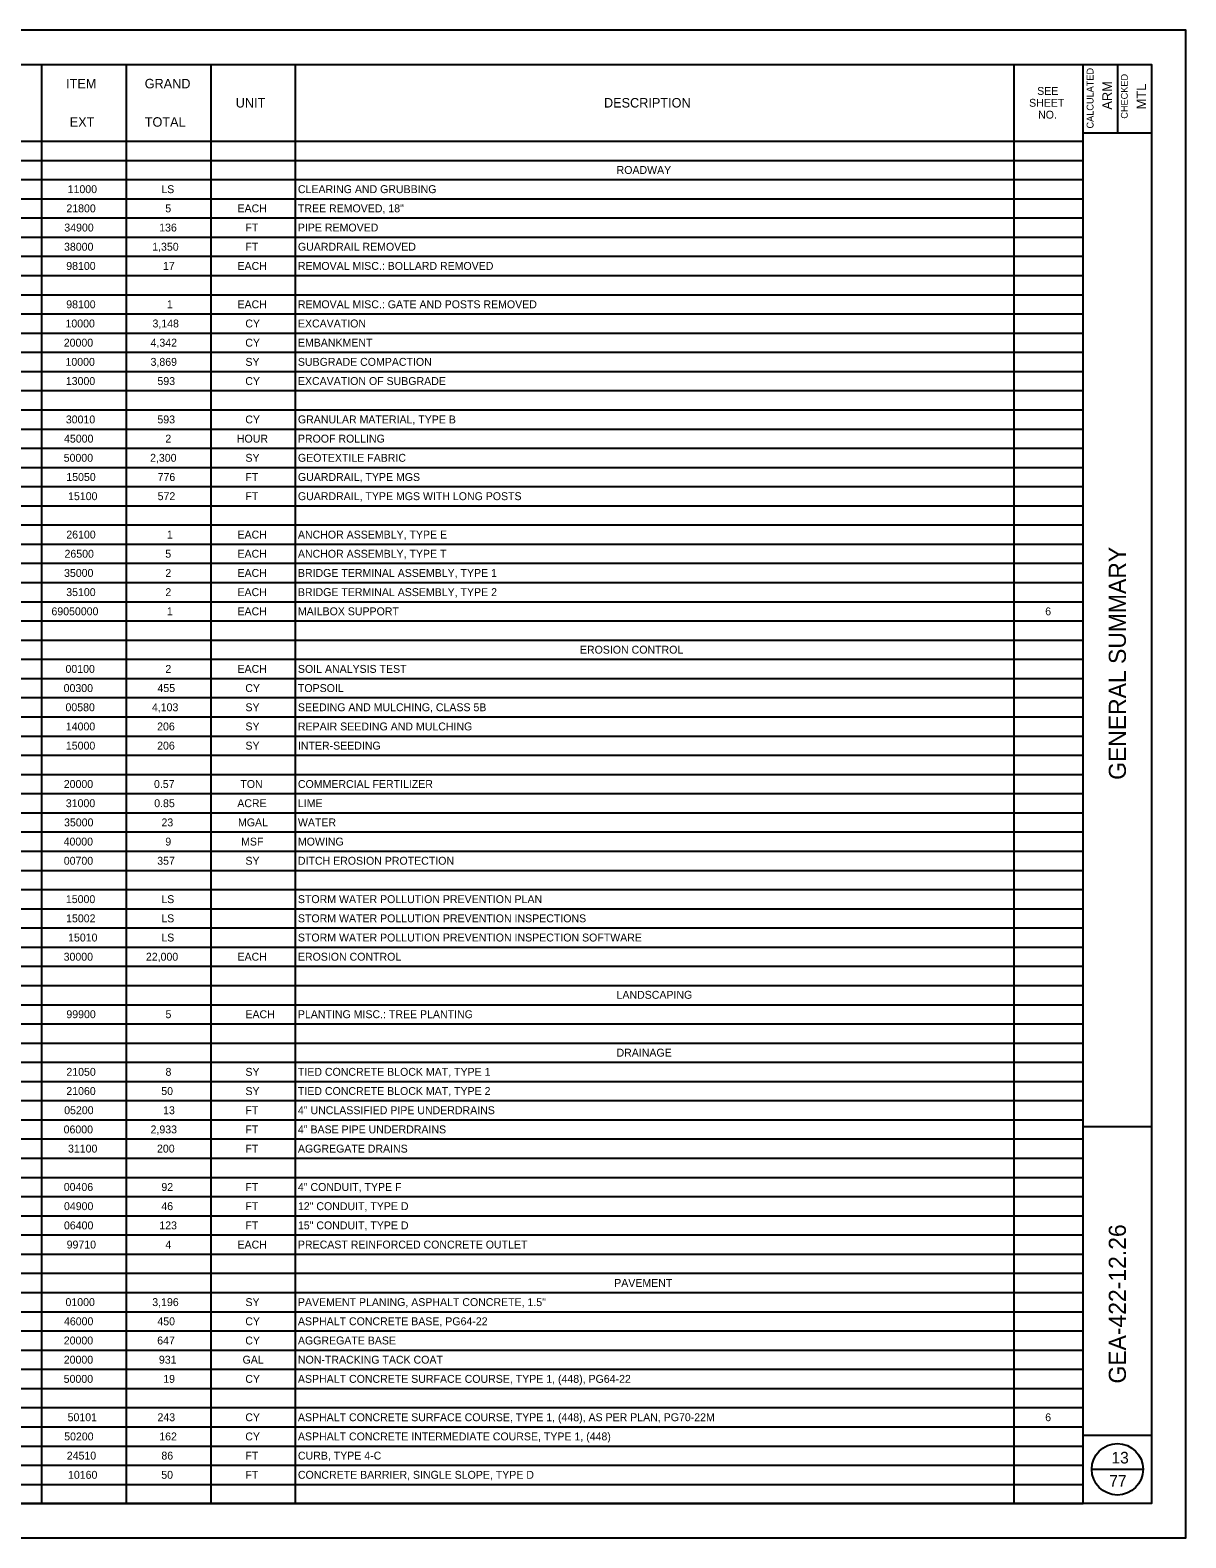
# Model space of a CAD drawing. Extents: x 0 to 34, y 0 to 22.
# Drawn here: x 17.13 to 34, y 0 to 22 of the extents above; entities that cross this region are included whole.
import ezdxf

# ---------------------------------------------------------------- set-up
doc = ezdxf.new("R2010")
doc.units = 0
for name, color, linetype in [('SH_Border', 7, 'Continuous'), ('SH_Cut_Line', 7, 'Continuous'), ('SH_Data', 7, 'Continuous'), ('SH_Text', 7, 'Continuous')]:
    doc.layers.add(name, color=color, linetype=linetype)

msp = doc.modelspace()

# ---------------------------------------------------------------- linework, layer by layer
at = {"layer": 'SH_Border'}
for p, q in [((32.5, 0.5), (32.5, 21.5)), ((33, 21.5), (33, 20.5)), ((32.5, 20.5), (33.5, 20.5)), ((32.5, 6), (33.5, 6)), ((32.5, 1.5), (33.5, 1.5))]:
    msp.add_line(p, q, dxfattribs=at)
msp.add_lwpolyline([(2, 21.5), (33.5, 21.5), (33.5, 0.5), (2, 0.5)], close=True, dxfattribs=at)
at = {"layer": 'SH_Cut_Line'}
msp.add_lwpolyline([(0, 0), (34, 0), (34, 22), (0, 22)], close=True, dxfattribs=at)
at = {"layer": 'SH_Data'}
msp.add_line((32.625, 1), (33.375, 1), dxfattribs=at)
msp.add_circle((33, 1), 0.375, dxfattribs=at)
at = {"layer": 'SH_Text'}
for p, q in [((2, 21.5), (32.5, 21.5)), ((17.299, 0.5), (17.299, 21.5)), ((18.535, 0.5), (18.535, 21.5)), ((19.77, 0.5), (19.77, 21.5)), ((21.005, 0.5), (21.005, 21.5)), ((31.495, 0.5), (31.495, 21.5)), ((32.5, 0.5), (32.5, 21.5)), ((14.055, 20.38), (32.5, 20.38)), ((19.77, 20.38), (32.5, 20.38)), ((2, 20.1), (32.5, 20.1)), ((2, 19.82), (32.5, 19.82)), ((2, 19.54), (32.5, 19.54)), ((2, 19.26), (32.5, 19.26)), ((2, 18.98), (32.5, 18.98)), ((2, 18.7), (32.5, 18.7)), ((2, 18.42), (32.5, 18.42)), ((2, 18.14), (32.5, 18.14)), ((2, 17.86), (32.5, 17.86)), ((2, 17.58), (32.5, 17.58)), ((2, 17.3), (32.5, 17.3)), ((2, 17.02), (32.5, 17.02)), ((2, 16.74), (32.5, 16.74)), ((2, 16.46), (32.5, 16.46)), ((2, 16.18), (32.5, 16.18)), ((2, 15.9), (32.5, 15.9)), ((2, 15.62), (32.5, 15.62)), ((2, 15.34), (32.5, 15.34)), ((2, 15.06), (32.5, 15.06)), ((2, 14.78), (32.5, 14.78)), ((2, 14.5), (32.5, 14.5)), ((2, 14.22), (32.5, 14.22)), ((2, 13.94), (32.5, 13.94)), ((2, 13.66), (32.5, 13.66)), ((2, 13.38), (32.5, 13.38)), ((2, 13.1), (32.5, 13.1)), ((2, 12.82), (32.5, 12.82)), ((2, 12.54), (32.5, 12.54)), ((2, 12.26), (32.5, 12.26)), ((2, 11.98), (32.5, 11.98)), ((2, 11.7), (32.5, 11.7)), ((2, 11.42), (32.5, 11.42)), ((2, 11.14), (32.5, 11.14)), ((2, 10.86), (32.5, 10.86)), ((2, 10.58), (32.5, 10.58)), ((2, 10.3), (32.5, 10.3)), ((2, 10.02), (32.5, 10.02)), ((2, 9.74), (32.5, 9.74)), ((2, 9.46), (32.5, 9.46)), ((2, 9.18), (32.5, 9.18)), ((2, 8.9), (32.5, 8.9)), ((2, 8.62), (32.5, 8.62)), ((2, 8.34), (32.5, 8.34)), ((2, 8.06), (32.5, 8.06)), ((2, 7.78), (32.5, 7.78)), ((2, 7.5), (32.5, 7.5)), ((2, 7.22), (32.5, 7.22)), ((2, 6.94), (32.5, 6.94)), ((2, 6.66), (32.5, 6.66)), ((2, 6.38), (32.5, 6.38)), ((2, 6.1), (32.5, 6.1)), ((2, 5.82), (32.5, 5.82)), ((2, 5.54), (32.5, 5.54)), ((2, 5.26), (32.5, 5.26)), ((2, 4.98), (32.5, 4.98)), ((2, 4.7), (32.5, 4.7)), ((2, 4.42), (32.5, 4.42)), ((2, 4.14), (32.5, 4.14)), ((2, 3.86), (32.5, 3.86)), ((2, 3.58), (32.5, 3.58)), ((2, 3.3), (32.5, 3.3)), ((2, 3.02), (32.5, 3.02)), ((2, 2.74), (32.5, 2.74)), ((2, 2.46), (32.5, 2.46)), ((2, 2.18), (32.5, 2.18)), ((2, 1.9), (32.5, 1.9)), ((2, 1.62), (32.5, 1.62)), ((2, 1.34), (32.5, 1.34)), ((2, 1.06), (32.5, 1.06)), ((2, 0.78), (32.5, 0.78)), ((2, 0.5), (32.5, 0.5))]:
    msp.add_line(p, q, dxfattribs=at)

# ---------------------------------------------------------------- texts
at = {"layer": 'SH_Data'}
for s, height, p in [('CALCULATED', 0.1, (32.652, 20.565)), ('CHECKED', 0.1, (33.152, 20.708)), ('ARM', 0.14, (32.92, 20.84)), ('MTL', 0.14, (33.42, 20.844)), ('GENERAL SUMMARY', 0.25, (33.125, 11.061)), ('GEA-422-12.26', 0.25, (33.125, 2.252))]:
    msp.add_text(s, height=height, rotation=90, dxfattribs=at).set_placement(p)
for s, p in [('13', (32.914, 1.085)), ('77', (32.882, 0.745))]:
    msp.add_text(s, height=0.17, dxfattribs=at).set_placement(p)
at = {"layer": 'SH_Text'}
for s, height, p in [('ITEM', 0.1384, (17.654, 21.151)), ('GRAND', 0.1384, (18.801, 21.151)), ('SEE', 0.1153, (31.83, 21.055)), ('UNIT', 0.1384, (20.13, 20.871)), ('DESCRIPTION', 0.13841, (25.506, 20.871)), ('SHEET', 0.1153, (31.712, 20.882)), ('EXT', 0.1384, (17.707, 20.591)), ('TOTAL', 0.1384, (18.802, 20.591)), ('NO.', 0.1153, (31.843, 20.709)), ('ROADWAY', 0.1153, (25.69, 19.902)), ('11000', 0.1153, (17.677, 19.622)), ('LS', 0.1153, (19.044, 19.622)), ('CLEARING AND GRUBBING ', 0.11534, (21.038, 19.622)), ('21800', 0.1153, (17.658, 19.342)), ('5', 0.115, (19.102, 19.342)), ('EACH', 0.1153, (20.156, 19.342)), ('TREE REMOVED, 18" ', 0.11534, (21.038, 19.342)), ('34900', 0.1153, (17.628, 19.062)), ('136', 0.1153, (19.013, 19.062)), ('FT', 0.1153, (20.272, 19.062)), ('PIPE REMOVED ', 0.11534, (21.038, 19.062)), ('38000', 0.1153, (17.624, 18.782)), ('1,350', 0.1153, (18.911, 18.782)), ('FT', 0.1153, (20.272, 18.782)), ('GUARDRAIL REMOVED ', 0.11534, (21.038, 18.782)), ('98100', 0.1153, (17.656, 18.502)), ('17', 0.1153, (19.068, 18.502)), ('EACH', 0.1153, (20.156, 18.502)), ('REMOVAL MISC.: BOLLARD REMOVED', 0.11534, (21.038, 18.502)), ('98100', 0.1153, (17.656, 17.942)), ('1', 0.115, (19.125, 17.942)), ('EACH', 0.1153, (20.156, 17.942)), ('REMOVAL MISC.: GATE AND POSTS REMOVED', 0.11534, (21.038, 17.942)), ('10000', 0.1153, (17.645, 17.662)), ('3,148', 0.1153, (18.915, 17.662)), ('CY', 0.1153, (20.27, 17.662)), ('EXCAVATION ', 0.11534, (21.038, 17.662)), ('20000', 0.1153, (17.62, 17.382)), ('4,342', 0.1153, (18.887, 17.382)), ('CY', 0.1153, (20.27, 17.382)), ('EMBANKMENT ', 0.11534, (21.038, 17.382)), ('10000', 0.1153, (17.645, 17.102)), ('3,869', 0.1153, (18.887, 17.102)), ('SY', 0.1153, (20.272, 17.102)), ('SUBGRADE COMPACTION ', 0.11534, (21.038, 17.102)), ('13000', 0.1153, (17.65, 16.822)), ('593', 0.1153, (18.987, 16.822)), ('CY', 0.1153, (20.27, 16.822)), ('EXCAVATION OF SUBGRADE ', 0.11534, (21.038, 16.822)), ('30010', 0.1153, (17.65, 16.262)), ('593', 0.1153, (18.987, 16.262)), ('CY', 0.1153, (20.27, 16.262)), ('GRANULAR MATERIAL, TYPE B ', 0.11534, (21.038, 16.262)), ('45000', 0.1153, (17.624, 15.982)), ('2', 0.115, (19.103, 15.982)), ('HOUR', 0.1153, (20.147, 15.982)), ('PROOF ROLLING ', 0.11534, (21.038, 15.982)), ('50000', 0.1153, (17.619, 15.702)), ('2,300', 0.1153, (18.88, 15.702)), ('SY', 0.1153, (20.272, 15.702)), ('GEOTEXTILE FABRIC ', 0.11534, (21.038, 15.702)), ('15050', 0.1153, (17.657, 15.422)), ('776', 0.1153, (18.99, 15.422)), ('FT', 0.1153, (20.272, 15.422)), ('GUARDRAIL, TYPE MGS ', 0.11534, (21.038, 15.422)), ('15100', 0.1153, (17.683, 15.142)), ('572', 0.1153, (18.99, 15.142)), ('FT', 0.1153, (20.272, 15.142)), ('GUARDRAIL, TYPE MGS WITH LONG POSTS ', 0.11534, (21.038, 15.142)), ('26100', 0.1153, (17.657, 14.582)), ('1', 0.115, (19.125, 14.582)), ('EACH', 0.1153, (20.156, 14.582)), ('ANCHOR ASSEMBLY, TYPE E ', 0.11534, (21.038, 14.582)), ('26500', 0.1153, (17.631, 14.302)), ('5', 0.115, (19.102, 14.302)), ('EACH', 0.1153, (20.156, 14.302)), ('ANCHOR ASSEMBLY, TYPE T ', 0.11534, (21.038, 14.302)), ('35000', 0.1153, (17.624, 14.022)), ('2', 0.115, (19.103, 14.022)), ('EACH', 0.1153, (20.156, 14.022)), ('BRIDGE TERMINAL ASSEMBLY, TYPE 1 ', 0.11534, (21.038, 14.022)), ('35100', 0.1153, (17.656, 13.742)), ('2', 0.115, (19.103, 13.742)), ('EACH', 0.1153, (20.156, 13.742)), ('BRIDGE TERMINAL ASSEMBLY, TYPE 2 ', 0.11534, (21.038, 13.742)), ('69050000', 0.1153, (17.44, 13.462)), ('1', 0.115, (19.125, 13.462)), ('EACH', 0.1153, (20.156, 13.462)), ('MAILBOX SUPPORT ', 0.11534, (21.038, 13.462)), ('6', 0.115, (31.947, 13.462)), ('EROSION CONTROL', 0.11534, (25.155, 12.902)), ('00100', 0.1153, (17.645, 12.622)), ('2', 0.115, (19.103, 12.622)), ('EACH', 0.1153, (20.156, 12.622)), ('SOIL ANALYSIS TEST ', 0.11534, (21.038, 12.622)), ('00300', 0.1153, (17.618, 12.342)), ('455', 0.1153, (18.988, 12.342)), ('CY', 0.1153, (20.27, 12.342)), ('TOPSOIL ', 0.1153, (21.038, 12.342)), ('00580', 0.1153, (17.645, 12.062)), ('4,103', 0.1153, (18.907, 12.062)), ('SY', 0.1153, (20.272, 12.062)), ('SEEDING AND MULCHING, CLASS 5B', 0.11534, (21.038, 12.062)), ('14000', 0.1153, (17.65, 11.782)), ('206', 0.1153, (18.983, 11.782)), ('SY', 0.1153, (20.272, 11.782)), ('REPAIR SEEDING AND MULCHING ', 0.11534, (21.038, 11.782)), ('15000', 0.1153, (17.651, 11.502)), ('206', 0.1153, (18.983, 11.502)), ('SY', 0.1153, (20.272, 11.502)), ('INTER-SEEDING ', 0.11534, (21.038, 11.502)), ('20000', 0.1153, (17.62, 10.942)), ('0.57', 0.1153, (18.937, 10.942)), ('TON', 0.1153, (20.198, 10.942)), ('COMMERCIAL FERTILIZER ', 0.11534, (21.038, 10.942)), ('31000', 0.1153, (17.65, 10.662)), ('0.85', 0.1153, (18.94, 10.662)), ('ACRE', 0.1153, (20.153, 10.662)), ('LIME ', 0.1153, (21.038, 10.662)), ('35000', 0.1153, (17.624, 10.382)), ('23', 0.1153, (19.046, 10.382)), ('MGAL', 0.1153, (20.163, 10.382)), ('WATER ', 0.1153, (21.038, 10.382)), ('40000', 0.1153, (17.618, 10.102)), ('9', 0.115, (19.102, 10.102)), ('MSF', 0.1153, (20.209, 10.102)), ('MOWING ', 0.1153, (21.038, 10.102)), ('00700', 0.1153, (17.62, 9.822)), ('357', 0.1153, (18.984, 9.822)), ('SY', 0.1153, (20.272, 9.822)), ('DITCH EROSION PROTECTION ', 0.11534, (21.038, 9.822)), ('15000', 0.1153, (17.651, 9.262)), ('LS', 0.1153, (19.044, 9.262)), ('STORM WATER POLLUTION PREVENTION PLAN ', 0.11534, (21.038, 9.262)), ('15002', 0.1153, (17.654, 8.982)), ('LS', 0.1153, (19.044, 8.982)), ('STORM WATER POLLUTION PREVENTION INSPECTIONS', 0.11534, (21.038, 8.982)), ('15010', 0.1153, (17.683, 8.702)), ('LS', 0.1153, (19.044, 8.702)), ('STORM WATER POLLUTION PREVENTION INSPECTION SOFTWARE', 0.11534, (21.038, 8.702)), ('30000', 0.1153, (17.618, 8.422)), ('22,000', 0.1153, (18.819, 8.422)), ('EACH', 0.1153, (20.156, 8.422)), ('EROSION CONTROL ', 0.11534, (21.038, 8.422)), ('LANDSCAPING', 0.11534, (25.689, 7.866)), ('99900', 0.1153, (17.658, 7.583)), ('5', 0.115, (19.105, 7.583)), ('EACH', 0.1153, (20.272, 7.583)), ('PLANTING MISC.: TREE PLANTING', 0.11534, (21.038, 7.583)), ('DRAINAGE', 0.1153, (25.689, 7.022)), ('21050', 0.1153, (17.658, 6.742)), ('8', 0.115, (19.105, 6.742)), ('SY', 0.1153, (20.272, 6.742)), ('TIED CONCRETE BLOCK MAT, TYPE 1 ', 0.11534, (21.038, 6.742)), ('21060', 0.1153, (17.657, 6.462)), ('50', 0.1153, (19.043, 6.462)), ('SY', 0.1153, (20.272, 6.462)), ('TIED CONCRETE BLOCK MAT, TYPE 2 ', 0.11534, (21.038, 6.462)), ('05200', 0.1153, (17.626, 6.182)), ('13', 0.1153, (19.07, 6.182)), ('FT', 0.1153, (20.272, 6.182)), ('4" UNCLASSIFIED PIPE UNDERDRAINS ', 0.11534, (21.038, 6.182)), ('06000', 0.1153, (17.618, 5.902)), ('2,933', 0.1153, (18.887, 5.902)), ('FT', 0.1153, (20.272, 5.902)), ('4" BASE PIPE UNDERDRAINS ', 0.11534, (21.038, 5.902)), ('31100', 0.1153, (17.682, 5.622)), ('200', 0.1153, (18.981, 5.622)), ('FT', 0.1153, (20.272, 5.622)), ('AGGREGATE DRAINS ', 0.11534, (21.038, 5.622)), ('00406', 0.1153, (17.62, 5.062)), ('92', 0.1153, (19.045, 5.062)), ('FT', 0.1153, (20.272, 5.062)), ('4" CONDUIT, TYPE F ', 0.11534, (21.038, 5.062)), ('04900', 0.1153, (17.623, 4.782)), ('46', 0.1153, (19.044, 4.782)), ('FT', 0.1153, (20.272, 4.782)), ('12" CONDUIT, TYPE D ', 0.11534, (21.038, 4.782)), ('06400', 0.1153, (17.623, 4.502)), ('123', 0.1153, (19.015, 4.502)), ('FT', 0.1153, (20.272, 4.502)), ('15" CONDUIT, TYPE D ', 0.11534, (21.038, 4.502)), ('99710', 0.1153, (17.662, 4.222)), ('4', 0.115, (19.104, 4.222)), ('EACH', 0.1153, (20.156, 4.222)), ('PRECAST REINFORCED CONCRETE OUTLET ', 0.11534, (21.038, 4.222)), ('PAVEMENT', 0.1153, (25.655, 3.662)), ('01000', 0.1153, (17.645, 3.382)), ('3,196', 0.1153, (18.912, 3.382)), ('SY', 0.1153, (20.272, 3.382)), ('PAVEMENT PLANING, ASPHALT CONCRETE, 1.5" ', 0.11534, (21.038, 3.382)), ('46000', 0.1153, (17.623, 3.102)), ('450', 0.1153, (18.986, 3.102)), ('CY', 0.1153, (20.27, 3.102)), ('ASPHALT CONCRETE BASE, PG64-22 ', 0.11534, (21.038, 3.102)), ('20000', 0.1153, (17.62, 2.822)), ('647', 0.1153, (18.984, 2.822)), ('CY', 0.1153, (20.27, 2.822)), ('AGGREGATE BASE ', 0.11534, (21.038, 2.822)), ('20000', 0.1153, (17.62, 2.542)), ('931', 0.1153, (19.009, 2.542)), ('GAL', 0.1153, (20.23, 2.542)), ('NON-TRACKING TACK COAT ', 0.11534, (21.038, 2.542)), ('50000', 0.1153, (17.619, 2.262)), ('19', 0.1153, (19.072, 2.262)), ('CY', 0.1153, (20.27, 2.262)), ('ASPHALT CONCRETE SURFACE COURSE, TYPE 1, (448), PG64-22 ', 0.11534, (21.038, 2.262)), ('50101', 0.1153, (17.676, 1.702)), ('243', 0.1153, (18.988, 1.702)), ('CY', 0.1153, (20.27, 1.702)), ('ASPHALT CONCRETE SURFACE COURSE, TYPE 1, (448), AS PER PLAN, PG70-22M', 0.11534, (21.038, 1.702)), ('6', 0.115, (31.947, 1.702)), ('ASPHALT CONCRETE INTERMEDIATE COURSE, TYPE 1, (448) ', 0.11534, (21.038, 1.422)), ('50200', 0.1153, (17.626, 1.422)), ('162', 0.1153, (19.014, 1.422)), ('CY', 0.1153, (20.27, 1.422)), ('24510', 0.1153, (17.664, 1.142)), ('86', 0.1153, (19.045, 1.142)), ('FT', 0.1153, (20.272, 1.142)), ('CURB, TYPE 4-C ', 0.11534, (21.038, 1.142)), ('10160', 0.1153, (17.682, 0.862)), ('50', 0.1153, (19.043, 0.862)), ('FT', 0.1153, (20.272, 0.862)), ('CONCRETE BARRIER, SINGLE SLOPE, TYPE D ', 0.11534, (21.038, 0.862))]:
    msp.add_text(s, height=height, dxfattribs=at).set_placement(p)

doc.saveas('drawing.dxf')
